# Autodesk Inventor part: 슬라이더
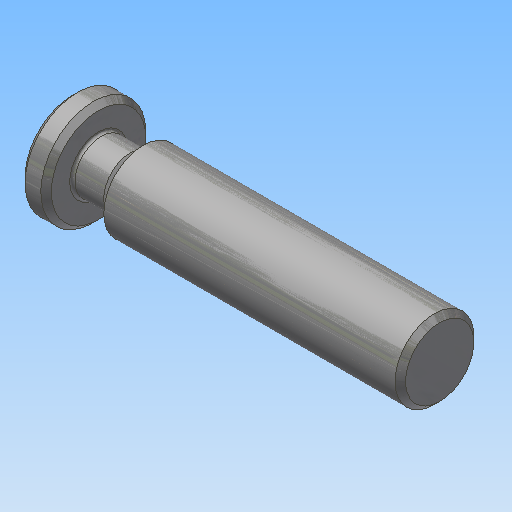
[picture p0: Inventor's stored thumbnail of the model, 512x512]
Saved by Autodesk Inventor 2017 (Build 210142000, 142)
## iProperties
Created: 2016-05
Part Number: 슬라이더
Document SubType Name: Modeling
Designer: mduedu
Density: 7.86 g/cm^3
Material: 강철, 연강
Appearance: 강철
Author: mduedu
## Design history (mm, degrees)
sketch "스케치1"
  geometry: L1 (-7.5, 0)-(62.5, 0); L2 (62.5, 0)-(62.5, 7.5); L3 (62.5, 7.5)-(0, 7.5); L4 (-7.5, 0)-(-7.5, 10); L5 (-7.5, 10)-(-2.5, 10); L6 (-2.5, 10)-(-2.5, 5); L7 (-2.5, 5)-(3.5, 5); L8 (3.5, 5)-(6, 7.5); A1 r 7.5 centre (0, 0) between (0, 7.5) and (-7.5, 0); 1 further point
  constraints: 16 end point, 3 perpendicular, 2 horizontal, 2 parallel, 2 point on circle, 2 point on line, 2 tangent, 1 centre point, 1 coincident
  dimensions: "d0" = 15 diameter of A1; "d1" = 70 distance of L1.start L1.end; "d19" = 20 diameter of L5 L1; "d20" = 10 diameter of L7 L1; "d21" = 5 distance of L4.end L5.end; "d22" = 135 deg angle of L8 L7; "d23" = 6 distance of L6.end L7.end
revolve "회전1" stored, may be unused: angle "d4" = 90 deg
chamfer "모따기2" distance "d24" = 1; stored, may be unused: second distance "d25" = 2, angle "d26" = 45 deg
fillet "모깎기1" dims "d27" = 0.5
node "솔리드1"
